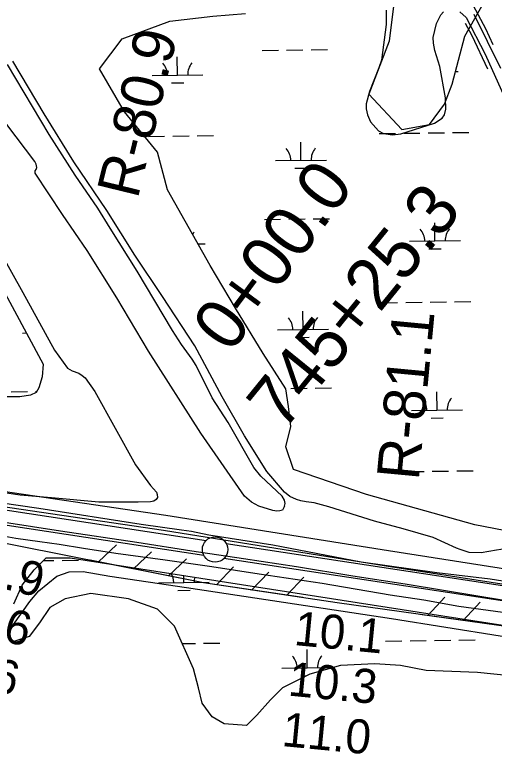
# Model space of a CAD drawing. Extents: x 3715084 to 3753216, y 488173 to 513963.
# Drawn here: x 3728178 to 3729121, y 501088 to 502523 of the extents above; entities that cross this region are included whole.
import ezdxf

# ---------------------------------------------------------------- set-up
doc = ezdxf.new("R2010")
doc.units = 0
for name, color, linetype in [('V-FLOD-BASE', 7, 'Continuous'), ('V-LEVE-TOET', 7, 'Continuous'), ('V-RIVR-RANG', 7, 'Continuous'), ('V-RIVR-RANG-IDEN', 7, 'Continuous'), ('V-ROAD-CNTR', 7, 'Continuous'), ('V-RRAP-FSHR', 7, 'Continuous'), ('V-SITE-VEGE', 7, 'Continuous'), ('V-SURV-IDEN', 7, 'Continuous'), ('V-SURV-LINE', 7, 'Continuous'), ('V-TOPO-SHOR', 7, 'Continuous'), ('V-WETL-SWMP', 7, 'Continuous')]:
    doc.layers.add(name, color=color, linetype=linetype)

msp = doc.modelspace()

# ---------------------------------------------------------------- linework, layer by layer
at = {"layer": 'V-FLOD-BASE'}
msp.add_lwpolyline([(3728101.8570000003, 501532.90400000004), (3728267.9250000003, 501507.679), (3728417.988, 501485.28), (3728525.819, 501467.973), (3728627.609, 501453.266), (3728731.631, 501437.386), (3728842.612, 501418.911), (3728945.323, 501403.42), (3729092.378, 501379.042), (3729216.214, 501358.908), (3729338.343, 501339.293), (3729435.279, 501325.61600000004), (3729508.865, 501315.132), (3729613.8030000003, 501300.30700000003), (3729742.866, 501284.386), (3729818.546, 501275.483), (3729848.7090000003, 501272.97000000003), (3729874.147, 501271.88300000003), (3729921.4760000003, 501271.53), (3729985.978, 501272.026), (3730082.981, 501275.264), (3730197.006, 501285.379)], dxfattribs=at)
at = {"layer": 'V-LEVE-TOET'}
for points in [[(3728035.076, 501579.658), (3728225.339, 501552.42600000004), (3728426.043, 501520.704), (3728505.335, 501509.389), (3728525.404, 501506.905), (3728559.646, 501499.753), (3728685.186, 501479.757), (3728858.951, 501446.759), (3729007.306, 501425.864), (3729112.364, 501413.461), (3729195.597, 501400.391), (3729277.245, 501390.659), (3729348.2800000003, 501378.919), (3729485.029, 501358.96400000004), (3729632.9930000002, 501336.884), (3729753.786, 501324.148), (3729823.418, 501319.288), (3729922.359, 501313.156), (3730004.182, 501308.734), (3730053.932, 501309.898), (3730125.293, 501317.039), (3730234.007, 501326.874)], [(3728092.669, 501508.836), (3728180.045, 501493.29000000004), (3728227.139, 501486.642), (3728264.918, 501481.403), (3728312.932, 501473.711), (3728376.688, 501463.848), (3728473.233, 501450.825), (3728565.059, 501437.392), (3728658.591, 501423.04600000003), (3728782.165, 501404.351), (3728915.589, 501381.631), (3728982.097, 501371.645), (3729050.582, 501359.306), (3729151.455, 501345.906)]]:
    msp.add_lwpolyline(points, dxfattribs=at)
at = {"layer": 'V-ROAD-CNTR'}
for points in [[(3729070.9043672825, 502552.0216687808), (3729078.743269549, 502540.4011995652), (3729103.071982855, 502495.18439329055), (3729117.918110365, 502463.89988737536)], [(3729063.3768564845, 502505.64515465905), (3729076.2940171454, 502481.6376067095), (3729107.4751308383, 502415.93119706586)], [(3728034.283892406, 501603.4237670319), (3728474.5000119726, 501538.28489731)], [(3728029.89190119, 501573.74782638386), (3728470.108020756, 501508.60895666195)], [(3728474.6570116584, 501538.26089735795), (3728912.663135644, 501468.68203651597), (3729598.3777642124, 501361.644250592), (3729765.140430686, 501348.3032772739), (3729904.9471510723, 501338.317297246), (3730027.6799056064, 501341.634290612), (3730110.469740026, 501348.258277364), (3730149.535661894, 501354.0752657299), (3730214.2135325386, 501361.63625060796)], [(3728469.95102107, 501508.632956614), (3728907.997144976, 501439.048095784), (3729594.86377124, 501331.83031022), (3729762.876435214, 501318.38933710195), (3729904.281152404, 501308.28935730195), (3730029.281902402, 501311.66635054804), (3730113.879733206, 501318.43433701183), (3730153.48765399, 501324.3333252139), (3730217.69752557, 501331.83831020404)]]:
    msp.add_lwpolyline(points, dxfattribs=at)
at = {"layer": 'V-RRAP-FSHR'}
for p, q in [((3728342.779, 501446.302), (3728378.046, 501480.076)), ((3728411.437, 501432.659), (3728446.704, 501466.433)), ((3728480.094, 501419.016), (3728515.361, 501452.79000000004)), ((3728574.3030000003, 501401.547), (3728607.926, 501436.95900000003)), ((3728643.532, 501391.181), (3728677.154, 501426.593)), ((3728712.7600000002, 501380.816), (3728746.382, 501416.227)), ((3728989.926, 501341.105), (3729023.198, 501376.846)), ((3729059.253, 501331.422), (3729092.525, 501367.163))]:
    msp.add_line(p, q, dxfattribs=at)
for points in [[(3728548.752, 501405.373), (3727726.447, 501568.773), (3727602.474, 501728.254), (3727577.733, 501759.099), (3727547.417, 501789.82300000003), (3727523.2490000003, 501814.996), (3727488.059, 501841.36100000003), (3727448.639, 501861.636), (3727409.291, 501877.971), (3727367.367, 501884.462), (3726990.911, 501928.14900000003), (3726789.781, 501978.82)], [(3728548.752, 501405.373), (3728326.1410000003, 501449.608)], [(3728743.866, 501376.158), (3728548.752, 501405.373)], [(3730161.524, 501239.07800000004), (3730106.904, 501229.283), (3730046.286, 501230.957), (3729994.281, 501233.026), (3729914.274, 501232.183), (3729853.183, 501234.92), (3729794.159, 501237.304), (3729721.532, 501244.205), (3729626.6070000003, 501253.407), (3729468.301, 501278.213), (3729223.757, 501308.445), (3728811.901, 501365.971), (3728548.752, 501405.373)], [(3730138.552, 501234.958), (3730106.904, 501229.283), (3730046.286, 501230.957), (3729994.281, 501233.026), (3729914.274, 501232.183), (3729853.183, 501234.92), (3729794.159, 501237.304), (3729721.532, 501244.205), (3729626.6070000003, 501253.407), (3729468.301, 501278.213), (3729223.757, 501308.445), (3728974.276, 501343.291)]]:
    msp.add_lwpolyline(points, dxfattribs=at)
at = {"layer": 'V-SITE-VEGE'}
for points in [[(3728908.126, 502531.8), (3728907.835, 502503.253), (3728899.0330000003, 502433.32800000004), (3728893.38, 502417.952), (3728875.237, 502371.816), (3728868.632, 502347.38), (3728868.47, 502337.53500000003), (3728871.071, 502325.732), (3728877.223, 502312.17), (3728893.04, 502293.917), (3728902.901, 502289.229), (3728920.631, 502286.33900000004), (3728936.572, 502288.17), (3729002.647, 502309.27900000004), (3729017.966, 502319.177), (3729022.666, 502325.88800000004), (3729025.384, 502336.923), (3729024.911, 502358.775), (3729013.4620000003, 502420.94800000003), (3729003.507, 502452.215), (3729000.697, 502466.575), (3729000.656, 502477.995), (3729006.858, 502504.99), (3729015.261, 502522.541), (3729020.948, 502528.271)], [(3729052.843, 502527.99700000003), (3729064.894, 502517.01300000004), (3729102.561, 502445.092), (3729157.9390000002, 502321.259)], [(3729133.6780000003, 502416.803), (3729081.255, 502523.053)], [(3728718.8540000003, 501575.077), (3728707.796, 501583.699), (3728673.1950000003, 501624.325), (3728629.233, 501694.45300000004), (3728585.643, 501770.882), (3728531.9220000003, 501871.683), (3728468.377, 501968.514), (3728414.136, 502050.02), (3728358.6920000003, 502137.431), (3728293.769, 502233.468), (3728235.544, 502327.75800000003), (3728174.1350000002, 502431.092)], [(3728145.123, 502062.439), (3728193.816, 501976.27), (3728255.793, 501863.2), (3728281.4930000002, 501827.298), (3728290.953, 501822.416), (3728303.755, 501817.742), (3728310.458, 501813.243), (3728316.3740000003, 501808.543), (3728335.355, 501781.468), (3728414.949, 501637.58400000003), (3728444.9930000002, 501596.77900000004), (3728456.449, 501583.447), (3728457.842, 501578.927), (3728458.452, 501573.422), (3728455.7120000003, 501569.48), (3728451.397, 501566.119), (3728444.913, 501564.523), (3728420.329, 501563.844), (3728342.833, 501564.153), (3728250.359, 501572.472), (3728188.575, 501577.95), (3728031.338, 501600.78500000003)], [(3729355.458, 501438.784), (3729344.806, 501444.849), (3729314.256, 501454.18700000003), (3729226.397, 501468.044), (3729150.582, 501473.674), (3729125.001, 501469.646), (3729094.698, 501464.614), (3729070.876, 501464.919), (3729053.7260000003, 501470.56700000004), (3729046.433, 501473.297), (3729000.4820000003, 501494.787), (3728941.555, 501511.308), (3728885.1920000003, 501526.658), (3728795.512, 501554.683), (3728766.148, 501562.451), (3728750.589, 501564.56), (3728739.95, 501566.293), (3728731.6720000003, 501569.01900000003), (3728718.8540000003, 501575.077)], [(3728139.159, 501273.31200000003), (3728207.265, 501368.634), (3728225.255, 501389.614), (3728260.802, 501418.268), (3728285.015, 501426.91000000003), (3728312.111, 501427.48600000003), (3728364.433, 501418.642), (3728515.207, 501395.897), (3728918.542, 501335.086), (3729238.65, 501283.958), (3729557.77, 501243.75800000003), (3729825.992, 501212.407), (3729982.41, 501206.316), (3730133.075, 501213.521), (3730246.1580000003, 501229.143)]]:
    msp.add_lwpolyline(points, dxfattribs=at)
at = {"layer": 'V-SURV-LINE'}
for points in [[(3727771.4476727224, 501608.153965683), (3728554.119471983, 501488.7792288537)], [(3728549.610744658, 501459.11997065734), (3727766.939244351, 501578.49466188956)], [(3728593.618966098, 501482.76035879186), (3729756.954803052, 501305.68285678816)], [(3729752.4540938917, 501276.0223812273), (3728589.1182569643, 501453.0998832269)]]:
    msp.add_lwpolyline(points, dxfattribs=at)
msp.add_circle((3728571.61712, 501470.9365999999), 25, dxfattribs=at)
at = {"layer": 'V-TOPO-SHOR'}
for points in [[(3728707.884, 501555.854), (3728709.24, 501561.57), (3728707.839, 501567.86600000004), (3728703.2830000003, 501575.724), (3728661.399, 501614.949), (3728647.948, 501632.425), (3728597.223, 501720.841), (3728565.94, 501769.164), (3728534.208, 501832.447), (3728526.483, 501845.216), (3728505.507, 501874.083), (3728487.688, 501901.581), (3728418.748, 502018.284), (3728365.475, 502102.951), (3728340.92, 502142.043), (3728296.384, 502207.053), (3728245.2970000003, 502286.806), (3728163.284, 502424.528)], [(3728271.6580000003, 502129.978), (3728218.007, 502210.903), (3728218.187, 502215.431), (3728219.948, 502218.393), (3728221.1180000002, 502221.94), (3728219.912, 502228.63), (3728217.1350000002, 502234.13300000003), (3728162.1350000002, 502306.979)], [(3728707.884, 501555.854), (3728704.169, 501548.55700000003), (3728698.662, 501546.962), (3728693.348, 501546.548), (3728685.074, 501547.699), (3728657.4790000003, 501556.065), (3728643.274, 501564.087), (3728629.448, 501575.851), (3728543.9420000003, 501699.974), (3728440.778, 501860.656), (3728378.179, 501965.962), (3728320.352, 502058.683), (3728271.6580000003, 502129.978)]]:
    msp.add_lwpolyline(points, dxfattribs=at)
at = {"layer": 'V-WETL-SWMP'}
for p, q in [((3728664.3319799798, 502452.47840399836), (3728696.3294813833, 502452.8782838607)), ((3728712.3282320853, 502453.0782237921), (3728744.325733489, 502453.47810365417)), ((3728760.324484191, 502453.67804358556), (3728792.3219855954, 502454.0779234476)), ((3728497.8612252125, 502403.96435651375), (3728497.411360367, 502439.9615455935)), ((3728447.865129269, 502403.3395442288), (3728547.8573211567, 502404.58916879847)), ((3729044.016200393, 502410.78977620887), (3729049.7261316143, 502410.86113448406)), ((3728486.054991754, 502388.3846064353), (3728510.0531178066, 502388.68451633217)), ((3728894.3948148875, 502288.83954860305), (3728926.392316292, 502289.2394284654)), ((3728942.3910669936, 502289.4393683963), (3728974.3885683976, 502289.83924825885)), ((3728990.3873190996, 502290.03918819), (3729022.384820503, 502290.4390680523)), ((3729038.383571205, 502290.63900798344), (3729070.381072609, 502291.03888784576)), ((3728440.5222565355, 502283.1674027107), (3728472.5197579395, 502283.56728257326)), ((3728488.5185086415, 502283.76722250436), (3728520.516010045, 502284.1671023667)), ((3728536.5147607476, 502284.36704229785), (3728568.512262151, 502284.76692216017)), ((3728740.448970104, 502236.1696909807), (3728739.999105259, 502272.16688006)), ((3728690.452874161, 502235.54487869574), (3728790.4450660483, 502236.79450326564)), ((3728728.642736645, 502220.58994090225), (3728752.6408626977, 502220.8898507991)), ((3728668.4891685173, 502119.82937963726), (3728700.486669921, 502120.2292594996)), ((3728716.485420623, 502120.429199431), (3728748.482922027, 502120.829079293)), ((3728764.4816727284, 502121.0290192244), (3728796.4791741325, 502121.4288990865)), ((3729003.887224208, 502077.58729783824), (3729003.437359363, 502113.584486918)), ((3728953.8911282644, 502076.9624855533), (3729053.8833201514, 502078.21211012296)), ((3728538.2773259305, 502071.7684678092), (3728552.0145096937, 502071.9401444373)), ((3728992.0809907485, 502062.0075477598), (3729016.0791168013, 502062.30745765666)), ((3728898.5520034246, 501956.19052424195), (3728930.549504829, 501956.59040410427)), ((3728946.548255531, 501956.79034403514), (3728978.5457569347, 501957.1902238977)), ((3728994.544507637, 501957.39016382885), (3729026.5420090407, 501957.7900436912)), ((3729042.5407597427, 501957.98998362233), (3729074.5382611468, 501958.38986348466)), ((3728744.606158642, 501903.52066661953), (3728744.156293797, 501939.5178556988)), ((3728694.610062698, 501902.8958543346), (3728794.6022545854, 501904.1454789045)), ((3728192.7418856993, 501896.62792188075), (3728200.45992329, 501896.724375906)), ((3728732.7999251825, 501887.9409165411), (3728756.7980512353, 501888.24082643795)), ((3728720.6426091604, 501787.7801750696), (3728752.6401105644, 501788.18005493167)), ((3728768.6388612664, 501788.37999486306), (3728800.63636267, 501788.7798747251)), ((3728170.7781005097, 501780.91246067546), (3728202.775587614, 501781.31234035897)), ((3728218.7743311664, 501781.5122802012), (3728220.9119153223, 501781.53899406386)), ((3729008.0444127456, 501744.93827347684), (3729007.5945479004, 501780.9354625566)), ((3728958.048316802, 501744.3134611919), (3729058.040508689, 501745.56308576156)), ((3728996.238179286, 501729.3585233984), (3729020.236305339, 501729.65843329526)), ((3728902.709191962, 501623.54149988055), (3728934.7066933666, 501623.9413797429)), ((3728950.7054440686, 501624.1413196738), (3728982.702945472, 501624.54119953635)), ((3728998.7016961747, 501624.7411394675), (3729030.6991975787, 501625.1410193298)), ((3729046.6979482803, 501625.34095926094), (3729078.6954496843, 501625.74083912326)), ((3728234.144320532, 501448.9993205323), (3728254.928488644, 501449.2590648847)), ((3728270.927239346, 501449.4590048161), (3728302.9247407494, 501449.85888467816)), ((3728510.332790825, 501406.0172834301), (3728510.159134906, 501419.9128456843)), ((3728460.3366948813, 501405.39247114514), (3728560.3288867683, 501406.6420957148)), ((3728498.5265573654, 501390.43753335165), (3728522.524683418, 501390.7374432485)), ((3728507.1984830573, 501285.89773728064), (3728532.987575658, 501286.2200292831)), ((3728548.9863263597, 501286.4199692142), (3728580.9838277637, 501286.8198490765)), ((3728906.8663805, 501290.89247551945), (3728938.8638819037, 501291.2923553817)), ((3728954.8626326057, 501291.49229531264), (3728986.8601340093, 501291.8921751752)), ((3729002.8588847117, 501292.09211510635), (3729034.856386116, 501292.4919949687)), ((3729050.855136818, 501292.69193489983), (3729082.852638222, 501293.0918147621)), ((3728752.9205357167, 501238.22261789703), (3728752.470670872, 501274.2198069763)), ((3728702.9244397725, 501237.5978056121), (3728802.9166316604, 501238.847430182)), ((3728741.1143022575, 501222.6428678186), (3728751.6572507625, 501222.7746253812))]:
    msp.add_line(p, q, dxfattribs=at)
for points in [[(3728923.643, 502549.57300000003), (3728913.739, 502470.344), (3728874.1240000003, 502366.355), (3728938.498, 502297.02900000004), (3728992.969, 502306.93200000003), (3729022.68, 502346.547), (3729037.535, 502386.162), (3729062.295, 502480.24700000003), (3729101.909, 502549.57300000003)], [(3730305.211, 501415.597), (3729938.774, 501395.79000000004), (3729567.384, 501425.501), (3729082.102, 501519.587), (3728869.1720000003, 501579.009), (3728725.568, 501628.527), (3728710.713, 501673.094), (3728720.616, 501712.70900000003), (3728715.664, 501752.324), (3728710.713, 501786.987), (3728666.146, 501856.313), (3728611.6750000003, 501945.446), (3728562.157, 502029.628), (3728477.975, 502178.184), (3728458.168, 502252.462), (3728393.793, 502331.69200000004), (3728344.275, 502415.873), (3728388.842, 502475.29600000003), (3728482.927, 502509.95900000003), (3728567.109, 502519.862), (3728631.483, 502524.814)], [(3728111.088, 502061.916), (3728233.841, 501835.023), (3728231.569, 501810.629), (3728225.356, 501788.581), (3728219.881, 501779.908), (3728208.8880000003, 501774.36100000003), (3728187.661, 501771.13800000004), (3728156.196, 501771.02400000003)], [(3728175.903, 501363.844), (3728192.724, 501400.851), (3728216.274, 501431.129), (3728239.824, 501454.679), (3728286.924, 501454.679), (3729107.81, 501326.836), (3729716.745, 501232.637), (3729763.845, 501225.908), (3729881.595, 501222.544), (3730036.352, 501232.637), (3730160.8310000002, 501232.637)], [(3729151.546, 501222.544), (3729087.6240000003, 501229.272), (3728986.696, 501232.637), (3728936.231, 501242.729), (3728885.767, 501246.094), (3728818.481, 501242.729), (3728757.924, 501225.908), (3728704.096, 501198.994), (3728680.546, 501175.444), (3728653.631, 501145.16500000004), (3728633.446, 501124.979), (3728589.71, 501128.344), (3728566.16, 501141.80100000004), (3728545.974, 501168.715), (3728539.2460000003, 501198.994), (3728529.153, 501236.001), (3728492.146, 501320.108), (3728458.503, 501353.751), (3728401.31, 501373.936), (3728327.296, 501384.02900000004), (3728276.832, 501373.936), (3728246.5530000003, 501357.115), (3728226.367, 501326.836), (3728206.182, 501299.922), (3728175.903, 501289.829)]]:
    msp.add_lwpolyline(points, dxfattribs=at)
for centre, radius, start, end in [((3728442.616669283, 502403.74879332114), 35.24628790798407, 359.94418071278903, 41.48783904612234), ((3728553.093914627, 502405.1294519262), 35.246287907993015, 139.9441777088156, 181.48783604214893), ((3728685.204414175, 502235.95412778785), 35.24628790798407, 359.94418071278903, 41.48783904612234), ((3728795.6816595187, 502237.33478639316), 35.246287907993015, 139.9441777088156, 181.48783604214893), ((3728557.251103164, 502072.4804275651), 35.246287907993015, 139.9441777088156, 148.11384813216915), ((3728948.642668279, 502077.3717346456), 35.24628790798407, 359.94418071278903, 41.48783904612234), ((3729059.119913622, 502078.7523932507), 35.246287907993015, 139.9441777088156, 181.48783604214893), ((3728689.361602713, 501903.3051034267), 35.24628790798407, 359.94418071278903, 41.48783904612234), ((3728799.838848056, 501904.68576203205), 35.246287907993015, 139.9441777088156, 181.48783604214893), ((3728952.7998568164, 501744.72271028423), 35.24628790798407, 359.94418071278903, 41.48783904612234), ((3729063.27710216, 501746.10336888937), 35.246287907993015, 139.9441777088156, 181.48783604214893), ((3728455.088234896, 501405.8017202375), 35.24628790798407, 359.94418071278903, 30.644028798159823), ((3728565.565480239, 501407.1823788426), 35.246287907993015, 164.54530305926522, 181.48783604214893), ((3728697.675979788, 501238.0070547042), 35.24628790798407, 359.94418071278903, 41.48783904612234), ((3728808.1532251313, 501239.38771330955), 35.246287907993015, 139.9441777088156, 181.48783604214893)]:
    msp.add_arc(centre, radius, start, end, dxfattribs=at)

# ---------------------------------------------------------------- texts
at = {"layer": 'V-RIVR-RANG'}
for s, height, rotation, p in [('9.9', 66.99999999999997, 346.15832571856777, (3728105.002628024, 501405.9284507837)), ('9.6', 66.99999999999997, 346.15832571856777, (3728079.7749109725, 501309.1540900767)), ('10.1', 66.99999999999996, 354.4583257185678, (3728725.2908279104, 501283.1722167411)), ('9.6', 66.99999999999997, 346.15832571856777, (3728056.083910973, 501212.0010900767)), ('10.3', 66.99999999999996, 354.4583257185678, (3728713.5159077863, 501183.8454748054)), ('11.0', 66.99999999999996, 354.4583257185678, (3728701.2168943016, 501084.56967910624))]:
    msp.add_text(s, height=height, rotation=rotation, dxfattribs=at).set_placement(p)
at = {"layer": 'V-RIVR-RANG-IDEN'}
for s, height, rotation, p in [('R-80.9', 82.99999799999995, 76.29584214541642, (3728419.308, 502158.564)), ('R-81.1', 82.99999800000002, 84.5996099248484, (3728971.8829180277, 501605.36510225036))]:
    msp.add_text(s, height=height, rotation=rotation, dxfattribs=at).set_placement(p)
at = {"layer": 'V-SURV-IDEN'}
for s, height, rotation, p in [('0+00.0', 99.99999999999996, 53.52115650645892, (3728601.607172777, 501854.41062099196)), ('745+25.3', 99.99999999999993, 50.9802101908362, (3728705.419892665, 501701.06952674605))]:
    msp.add_text(s, height=height, rotation=rotation, dxfattribs=at).set_placement(p)

doc.saveas('drawing.dxf')
